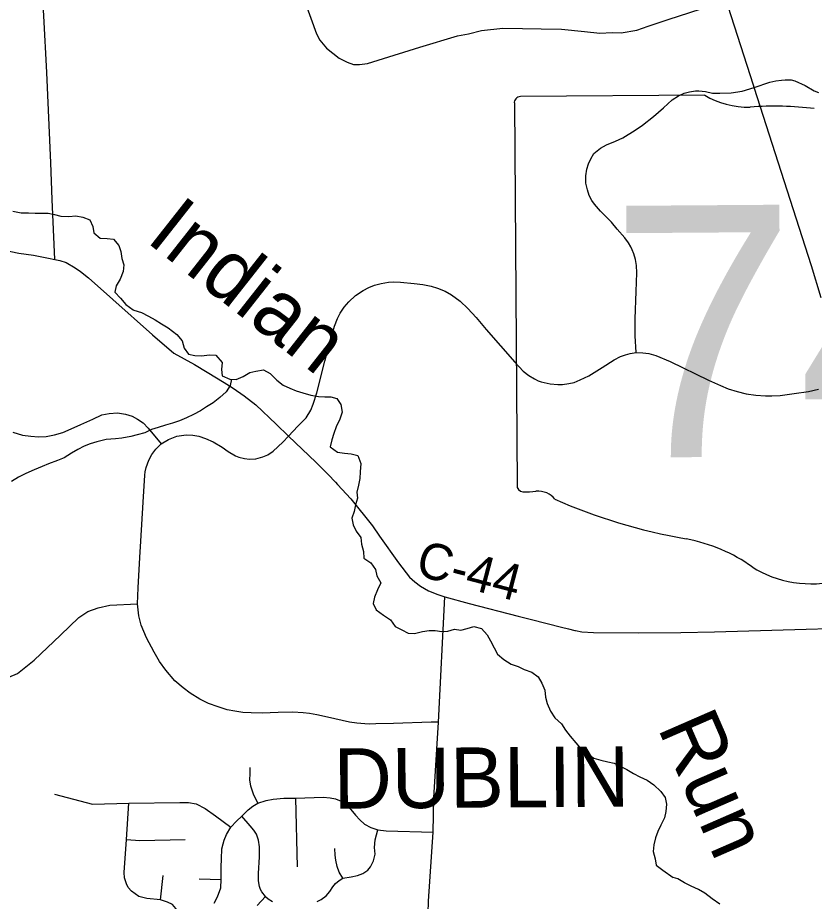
# Model space of a CAD drawing. Extents: x 114604 to 551442, y 316898 to 567001.
# Drawn here: x 165573 to 172180, y 441321 to 448649 of the extents above; entities that cross this region are included whole.
import ezdxf

# ---------------------------------------------------------------- set-up
doc = ezdxf.new("R2010")
doc.units = 0
for name, color, linetype in [('_CIVIL_CONSTRUCTION', 7, 'Continuous'), ('BD_X_Building', 7, 'Continuous'), ('GE_P_Alignment_100_Cardinal_Points', 7, 'Continuous'), ('GE_P_Alignment_500_Bearings', 7, 'Continuous'), ('GE_P_Alignment_500_Curve_Data', 7, 'Continuous'), ('PM_P_Cells', 7, 'Continuous'), ('PM_P_CL_Double_Solid', 7, 'Continuous'), ('PM_P_Stop_Line', 7, 'Continuous'), ('SH_Named_Boundary', 7, 'Continuous')]:
    doc.layers.add(name, color=color, linetype=linetype)

msp = doc.modelspace()

# ---------------------------------------------------------------- linework, layer by layer
at = {"layer": '_CIVIL_CONSTRUCTION'}
msp.add_lwpolyline([(172237.8, 446325.8), (172155.6, 446590.9), (171680.8, 448069.5), (171674.2, 448090.1), (170653.6, 451268.7)], dxfattribs=at)
at = {"layer": 'GE_P_Alignment_100_Cardinal_Points'}
for p, q in [((167893.8, 441608.3), (167880.7, 442176.8)), ((166757.7, 441332.1), (166779.1, 441533.8)), ((167078.6, 441506.9), (167261.9, 441500.6))]:
    msp.add_line(p, q, dxfattribs=at)
for points in [[(165880.6, 446644.8), (165859.8, 447142.2), (165847.8, 447445.3), (165815.5, 448195.8), (165791.3, 448663.4), (165767.1, 449028.6)], [(167956.6, 448775), (168051.6, 448516.6), (168078.5, 448462), (168133.3, 448396.7), (168239.7, 448312.5), (168305.1, 448279.2), (168356.8, 448260.2), (168408.8, 448261.2), (168473, 448268), (168561.6, 448296.4), (168907.8, 448404.1), (169219.8, 448498.3), (169312.2, 448516.6), (169418.8, 448542.7), (169597.2, 448561.3), (169759.3, 448560.2), (169913.3, 448557.3), (170083.3, 448554.1), (170275, 448534.4), (170400.8, 448519.9), (170503, 448526), (170577, 448524.6), (170707.5, 448546.2), (170802.1, 448578.4), (170967.3, 448633.4), (171422.5, 448779.8)], [(171680.8, 448069.5), (171812.1, 448113.3), (171861.9, 448124.2), (171906.6, 448131.7), (171937.5, 448134.7), (171987, 448132.5), (172019.5, 448124.2), (172104.9, 448087.2), (172179.9, 448042.3), (172213.2, 448028.5)], [(170701.2, 445873.1), (170694.5, 446011.1), (170694, 446081.9), (170695.1, 446152.7), (170703.3, 446377.4), (170708.6, 446532.9), (170704.9, 446594.7), (170697.3, 446644.3), (170683.1, 446689.8), (170669, 446724.7), (170657.4, 446749), (170639.3, 446782.3), (170608.1, 446824.4), (170544.1, 446896.3), (170497.2, 446953.8), (170405.4, 447043.5), (170357, 447103.4), (170334.8, 447132.5), (170312.5, 447175.5), (170297.5, 447221.8), (170284.9, 447277), (170285.3, 447338.1), (170293.1, 447391.8), (170307.4, 447438.3), (170325.8, 447478.4), (170351.5, 447522.5), (170406.6, 447567.7), (170457.6, 447595.7), (170529.9, 447624.7), (170593.1, 447653.6), (170695.2, 447715.4), (170755.2, 447756.6), (170845, 447829.6), (170928.3, 447901.9), (171000.3, 447968.3), (171052.1, 448000.4), (171101.6, 448022.8), (171144.7, 448035.3), (171193.4, 448043), (171222.8, 448041.5), (171276.5, 448036.2), (171335.2, 448024.4), (171397.1, 448022.5), (171491.5, 448024.8), (171581.7, 448039.2), (171680.8, 448069.5)], [(167820.1, 445179.3), (167896.5, 445260.7), (167966.2, 445331.4), (168004, 445393.3), (168024.9, 445443.4), (168052.9, 445539.3), (168121.2, 445799.3), (168180.2, 446023), (168199.9, 446090.1), (168225, 446154.1), (168248, 446198.9), (168279.6, 446249.1), (168319.7, 446294), (168374.6, 446344.4), (168438.1, 446386.3), (168485.7, 446412.2), (168533.5, 446429.5), (168587.6, 446444.8), (168647, 446454.8), (168688.5, 446457.2), (168749.1, 446455.5), (168860.8, 446445.7), (168934.3, 446435.6), (169001.3, 446422.3), (169053.5, 446406.7), (169117.5, 446381.6), (169170.9, 446351.2), (169242.5, 446298.5), (169306.8, 446238.4), (169375.3, 446163.4), (169457.9, 446064.1), (169694.8, 445793.6), (169766.6, 445717.5), (169811.5, 445681.7), (169858.5, 445653.3), (169888.4, 445638.7), (169915.1, 445630.4), (169989.6, 445611.8), (170052.4, 445606.9), (170092.8, 445606.1), (170144.8, 445615), (170189.4, 445623.8), (170239.2, 445644.4), (170310.2, 445677.9), (170419.3, 445746.7), (170520.9, 445812.3), (170571.7, 445838.2), (170614.1, 445854.4), (170652.3, 445864.3), (170701.2, 445873.1), (170758.6, 445869.3), (170808.6, 445864.3), (170865.1, 445847.7), (170983.5, 445796.5), (171303.6, 445642.5), (171402.8, 445599.6), (171465.7, 445572.4), (171539.2, 445549.6), (171614.8, 445531), (171693.6, 445518.8), (171774.5, 445513), (171828.7, 445513.4), (171895.6, 445516), (172011.4, 445532.8), (172132.5, 445549.6), (172213.2, 445568.2)], [(165533.6, 445210.8), (165612.7, 445187.6), (165682.4, 445177.9), (165746.1, 445174.1), (165809.8, 445177.2), (165877.7, 445188.7), (165948, 445209.6), (166042, 445251), (166097, 445274.3), (166195.2, 445320.9), (166272.3, 445354.6), (166330.8, 445366.1), (166400.4, 445370.8), (166465.9, 445361.1), (166522, 445344.5), (166568.1, 445319.4), (166615, 445288.3), (166656.1, 445246.1), (166762.4, 445115.7)], [(169062, 442807), (169002.8, 442806.7), (168689.9, 442795.2), (168542.6, 442792.1), (168487.4, 442790.7), (168452.6, 442792.5), (168387.1, 442797.2), (168323.6, 442808), (168141.2, 442847.6), (168055.2, 442867.4), (167993.7, 442878.2), (167940.5, 442885), (167854.5, 442888.5), (167732.8, 442885.5), (167600.9, 442881.5), (167508.8, 442882.9), (167440.3, 442887.5), (167373.7, 442897.3), (167310.2, 442910.1), (167235.3, 442933.1), (167155.4, 442961.2), (167084.5, 442997.5), (167004.4, 443048.1), (166944.7, 443092.6), (166876.8, 443150.4), (166802.5, 443236.9), (166749.8, 443309.1), (166705.3, 443387.6), (166641, 443506.8), (166598.3, 443610.8), (166578.3, 443687.4), (166567.4, 443787.5), (166571.5, 443921.6), (166587.1, 444173.3), (166595.3, 444307.4), (166614.5, 444630.8), (166628.2, 444854.9), (166631.1, 444883.6), (166639, 444918.4), (166660, 444978.9), (166686.3, 445027.2), (166718.7, 445070.4), (166762.4, 445115.7), (166824.5, 445150.9), (166893.9, 445178), (166971.6, 445188.8), (167025.8, 445187.1), (167076, 445177.3), (167131.3, 445159.3), (167192.9, 445131.1), (167267.9, 445086.6), (167318.3, 445052.2), (167378.9, 445015.8), (167407.6, 445003.7), (167454.8, 444992.8), (167495.7, 444988), (167547.9, 444991.4), (167605, 445006.2), (167647.9, 445022.8), (167691.6, 445053.8), (167770.9, 445128.1), (167820.1, 445179.3)], [(168941.3, 440483.1), (168944, 440522.5), (168961.3, 440804.2), (168970.6, 441024.2), (168980, 441321), (169017.9, 441893.2), (169024.7, 442179.6), (169062, 442807), (169114.2, 443846.6)], [(163421.4, 442867.2), (163707.1, 442751.6), (163836.4, 442714.3), (164070.4, 442706.5), (164271.2, 442688.8), (164342.7, 442708.4), (164752.3, 442864.2), (165571.3, 443209.2), (165709, 443320), (165927.2, 443527), (166078.9, 443676.1), (166155, 443724.4), (166240.8, 443753.7), (166336.1, 443778.3), (166567.4, 443787.5)], [(167564.3, 442136), (167528.2, 442210.1), (167505.9, 442277), (167499.1, 442328.6), (167501.2, 442378.8), (167500, 442431.3)], [(165877.3, 442210.1), (166192.7, 442126.5), (166494.7, 442135.1), (166917.5, 442141.3), (166990.7, 442141.8), (167054.3, 442129.5), (167127.8, 442091.9), (167214.1, 442028.9), (167339.7, 441937)], [(166991.5, 441097.1), (166929.7, 441189.8), (166917.3, 441217.2), (166883.4, 441262.7), (166857.2, 441294.6), (166815.8, 441314.2), (166757.7, 441332.1), (166643.1, 441345), (166578.8, 441361.3), (166515.9, 441405.1), (166488.2, 441435.5), (166475.8, 441465.9), (166460.2, 441516.2), (166456.8, 441558.9), (166476.2, 441833.9), (166494.7, 442135.1)], [(167203.7, 441304.7), (167229.3, 441358.4), (167257.8, 441431.9), (167261.9, 441500.6), (167261.1, 441604.4), (167262.9, 441672.4), (167266.9, 441755.6), (167277.3, 441797.7), (167285.5, 441827.5), (167304.2, 441875), (167339.7, 441937), (167388.4, 441986.8), (167432.6, 442026), (167484.7, 442080.5), (167522.5, 442109.8), (167564.3, 442136), (167632.8, 442156), (167693.2, 442169.1), (167779, 442176.1), (167880.7, 442176.8), (168106.6, 442184.3), (168163.8, 442179.8), (168209.7, 442170.3), (168255.6, 442151), (168298.3, 442121.9), (168336.2, 442082.9), (168375.8, 442034.2), (168410.4, 441996.8), (168450, 441959.5), (168500.8, 441933.7), (168559.9, 441912.8), (168628.6, 441905.2), (169017.9, 441893.2)], [(167629.3, 441360), (167597.1, 441399.8), (167587.1, 441420.2), (167579.8, 441444.4), (167571.1, 441489.5), (167570.6, 441551.7), (167579.6, 441690), (167579, 441774.1), (167571.4, 441828.2), (167554.1, 441876.5), (167532, 441911.9), (167501.8, 441947.3), (167432.6, 442026)], [(168057.2, 441320.5), (168090.6, 441335.5), (168130.4, 441366.8), (168161.2, 441403), (168186.3, 441440.8), (168209, 441468.8), (168239.1, 441493.5), (168270, 441511.7), (168338.6, 441523.7), (168392.5, 441533.9), (168436.5, 441550.6), (168477.2, 441580.3), (168498.3, 441606.6), (168524.1, 441655.8), (168536.8, 441713.2), (168533.1, 441767.1), (168537.6, 441830.9), (168559.9, 441912.8)], [(166476.2, 441833.9), (166586.2, 441825.5), (166963.3, 441834.4)], [(168270, 441511.7), (168238.6, 441562.2), (168223.5, 441609.5), (168211.7, 441661.8), (168206.5, 441704.3), (168204.5, 441758.2)], [(167560.4, 441286.8), (167629.3, 441360), (167651.5, 441340.5), (167686.8, 441320.3)]]:
    msp.add_lwpolyline(points, dxfattribs=at)
at = {"layer": 'GE_P_Alignment_500_Bearings'}
msp.add_line((170141.6, 443579.7), (170194.1, 443567.4), dxfattribs=at)
for points in [[(161500.4, 448042.2), (161608.2, 448027.1), (161718.8, 447995.9), (162080.1, 447868.2), (162508.3, 447711.5), (163253.9, 447412.7), (163613.8, 447280), (163899.8, 447182.1), (164182.4, 447069), (164493.3, 446953), (164654.5, 446891.6), (164723.7, 446866.1), (164832, 446837), (165314.6, 446750.7), (165583.1, 446697.1), (165705.6, 446678.4), (165829.1, 446654.7)], [(165829.1, 446654.7), (165880.6, 446644.8), (165921.9, 446636), (165974, 446618), (166049.5, 446574.5), (166094.5, 446545.2), (166159.7, 446491.3), (166361, 446311.9), (166691.9, 446018.3), (166869, 445868.2), (167040.5, 445771.8), (167145.6, 445710.1), (167285.1, 445624.7), (167361.1, 445576), (167451.8, 445513.6), (167547, 445437.3), (167716.6, 445277), (167820.1, 445179.3), (168046.3, 444962), (168149.2, 444861.2), (168208.6, 444797.7)], [(168208.6, 444797.7), (168226.1, 444779.1), (168336.2, 444657.5), (168516, 444436.2), (168574.2, 444349.2), (168731.7, 444127.7), (168823.5, 444009), (168865.9, 443971.2), (168913.8, 443934.8), (168980.2, 443896.7), (169058.3, 443866.3), (169114.2, 443846.6)], [(169114.2, 443846.6), (169317.1, 443791.5), (169723.1, 443686.2), (169834.9, 443657.4)], [(169834.9, 443657.4), (170083.9, 443593.2), (170141.6, 443579.7)], [(170194.1, 443567.4), (170199.3, 443566.2), (170252, 443557.1), (170348.2, 443550.2), (170725.5, 443547.2), (171071.8, 443550.3), (171351, 443554.9), (173064.4, 443606)]]:
    msp.add_lwpolyline(points, dxfattribs=at)
at = {"layer": 'GE_P_Alignment_500_Curve_Data'}
for p, q in [((171272.4, 448006.3), (169743.5, 447995.3)), ((169692.5, 447940.4), (169715.4, 444770.5))]:
    msp.add_line(p, q, dxfattribs=at)
for centre, major_axis, start_param, end_param in [((169752.3, 447947.5), (60.5, 0.4), 1.712693, 3.28349), ((171633.9, 448376.9), (586.6, 4.2), 4.042523, 4.731795), ((171843.8, 446230.7), (2106, 15.2), 1.404758, 1.657858), ((169775.8, 444764), (61, 0.4), 3.00124, 4.508301), ((169782.7, 445088.3), (465.6, 3.4), 4.665946, 4.897461), ((169881.6, 444588.8), (167.9, 1.2), 0.519207, 1.627899), ((171980.8, 447452.1), (3998, 28.8), 4.195995, 4.488959), ((170818.3, 443354.3), (1250.9, 9), 0.823519, 1.323588), ((172162.4, 444589.5), (793.8, 5.7), 4.026481, 4.996735)]:
    msp.add_ellipse(centre, major_axis=major_axis, ratio=0.8, start_param=start_param, end_param=end_param, dxfattribs=at)
at = {"layer": 'PM_P_Cells'}
for points in [[(165533, 447043.4), (165600.9, 447032.1), (165663, 447030.9), (165719, 447027.8), (165777.2, 447028.7), (165827.2, 447027.7), (165879.1, 447016.7), (165930.9, 447003.6), (165997, 447000.4), (166055.2, 447005.3), (166113.1, 446996.1), (166172.8, 446972.9), (166195.8, 446918.2), (166204.8, 446863.9), (166256.1, 446820.8), (166314.1, 446817.6), (166368.1, 446812.6), (166411.2, 446759.6), (166428.2, 446709.1), (166437.2, 446652.7), (166454.2, 446598.2), (166449.2, 446544.1), (166424, 446480.4), (166388.9, 446424.9), (166379.9, 446372.9), (166427, 446321.8), (166470.2, 446270.8), (166531.4, 446225.4), (166535.4, 446223.4)], [(166535.4, 446223.4), (166599, 446205), (166658.8, 446174.6), (166712.7, 446144.2), (166766.5, 446109.8), (166820.3, 446077.4), (166894, 446020.8), (166937.7, 445968.4), (166953.4, 445908.1), (166989.1, 445857.8), (167041, 445847.5), (167099, 445845.1), (167161.1, 445852.8), (167215.1, 445850.5), (167268.7, 445790), (167264.4, 445731.9), (167270.1, 445677.7), (167332, 445651.2), (167384, 445648.9), (167442.1, 445672.6), (167498.3, 445706.4), (167548.4, 445718.1), (167610.4, 445727.8), (167666.3, 445697.4), (167722, 445642.9), (167775.7, 445600.5), (167829.6, 445576.1), (167881.5, 445555.7), (167937.4, 445537.4), (168005.3, 445518.9), (168067.2, 445506.5), (168119.2, 445504.2), (168169.3, 445505.9), (168221.2, 445491.6), (168252.9, 445441.2), (168264.5, 445377), (168244.2, 445319), (168213.8, 445255), (168195.5, 445201), (168177.2, 445149), (168164.9, 445088.9), (168224.6, 445046.4), (168282.6, 445038.1), (168338.6, 445031.7), (168394.5, 445019.3), (168420.1, 444953), (168413.7, 444882.9), (168409.4, 444828.8), (168399.1, 444772.7), (168384.8, 444714.6), (168390.5, 444664.5), (168374.2, 444610.4), (168363.9, 444554.3), (168345.5, 444498.3), (168355.2, 444444.1), (168380.9, 444389.8), (168418.6, 444337.5), (168424.3, 444283.3), (168440, 444221), (168443.7, 444166.9), (168501.5, 444128.4), (168541.2, 444074.1), (168550.9, 444019.9), (168584.5, 443961.5), (168558.2, 443905.5), (168531.9, 443843.5), (168521.5, 443789.5), (168547.2, 443737.2), (168607, 443694.7), (168664.8, 443654.3), (168704.5, 443599.9), (168758.3, 443571.5), (168810.2, 443545.1), (168864.2, 443542.8), (168930.3, 443558.4), (168984.3, 443568.1), (169036.3, 443567.8), (169090.3, 443557.5), (169140.3, 443561.2), (169196.4, 443576.9), (169248.4, 443570.6), (169300.5, 443584.3), (169356.6, 443600), (169418.5, 443583.6), (169466.2, 443531.2), (169493.9, 443480.9), (169523.6, 443422.6), (169553.3, 443370.3), (169605, 443325.8), (169664.8, 443287.4), (169722.7, 443267), (169774.6, 443242.6), (169836.5, 443222.2), (169890.3, 443183.8), (169920, 443129.5), (169943.7, 443073.2), (169951.3, 443013), (169963, 442960.8), (169990.7, 442898.5), (170028.4, 442842.1), (170082.1, 442793.6)], [(167346.8, 445650.6), (167335.7, 445599.1), (167301.4, 445547.2), (167249.1, 445499.4), (167194.8, 445455.6), (167138.6, 445421.8), (167088.4, 445390), (167032.3, 445358.3), (166974.1, 445330.6), (166915.9, 445306.8), (166855.8, 445287.1), (166799.7, 445269.4), (166737.6, 445251.8), (166681.5, 445234), (166627.3, 445206.3), (166565.2, 445188.6), (166511.1, 445174.9), (166437, 445161.3), (166383, 445155.6), (166307, 445150.1), (166230.8, 445132.5), (166174.7, 445114.8), (166124.6, 445095), (166072.5, 445067.2), (166018.3, 445037.5), (165958.1, 444999.7), (165903.9, 444976), (165829.8, 444950.4), (165775.6, 444926.6), (165709.4, 444899), (165639.3, 444869.3), (165579.1, 444837.6), (165520.9, 444801.8)], [(170082.1, 442793.6), (170115.8, 442741.3), (170155.5, 442691), (170203.2, 442634.5), (170246.9, 442584.1), (170298.7, 442543.7), (170352.5, 442507.3), (170408.4, 442490.9), (170466.3, 442476.6), (170520.3, 442466.2), (170574.1, 442439.8), (170626, 442415.5), (170679.8, 442381.1), (170731.7, 442352.7), (170793.5, 442326.2), (170849.3, 442287.8), (170907, 442231.3), (170942.7, 442181), (170954.4, 442126.8), (170948.1, 442064.6), (170937.8, 442012.6), (170907.4, 441952.6), (170881.1, 441898.6), (170862.8, 441846.6), (170848.5, 441790.5), (170844.2, 441734.4), (170859.8, 441672.2), (170869.5, 441620), (170923.3, 441579.6), (171008.3, 441518.9)], [(171048.3, 441508.6), (171008.3, 441518.9)], [(171395.2, 441297.3), (171333.5, 441341.9), (171271.7, 441388.5), (171219.9, 441419), (171158, 441447.6), (171104.1, 441474), (171048.3, 441508.6)]]:
    msp.add_lwpolyline(points, dxfattribs=at)

# ---------------------------------------------------------------- texts
at = {"layer": 'BD_X_Building'}
msp.add_text('745', height=1, rotation=0.41273, dxfattribs=at).set_placement((171905, 446088.8))
at = {"layer": 'GE_P_Alignment_500_Curve_Data'}
msp.add_text('745', height=2088.33, rotation=0.41273, dxfattribs=at).set_placement((170492.1, 444999.6))
at = {"layer": 'PM_P_CL_Double_Solid'}
msp.add_text('C-44', height=300.01, rotation=345.35651, dxfattribs=at).set_placement((168861.8, 444028.5))
at = {"layer": 'PM_P_Stop_Line'}
for s, height, rotation, p in [('Indian', 499.99, 321.78842, (166626.5, 446798.8)), ('Run', 499.97, 293.54192, (170876.4, 442763.7))]:
    msp.add_text(s, height=height, rotation=rotation, dxfattribs=at).set_placement(p)
at = {"layer": 'SH_Named_Boundary'}
msp.add_text('DUBLIN', height=500.01, rotation=0.41259, dxfattribs=at).set_placement((168194.7, 442089))

doc.saveas('drawing.dxf')
